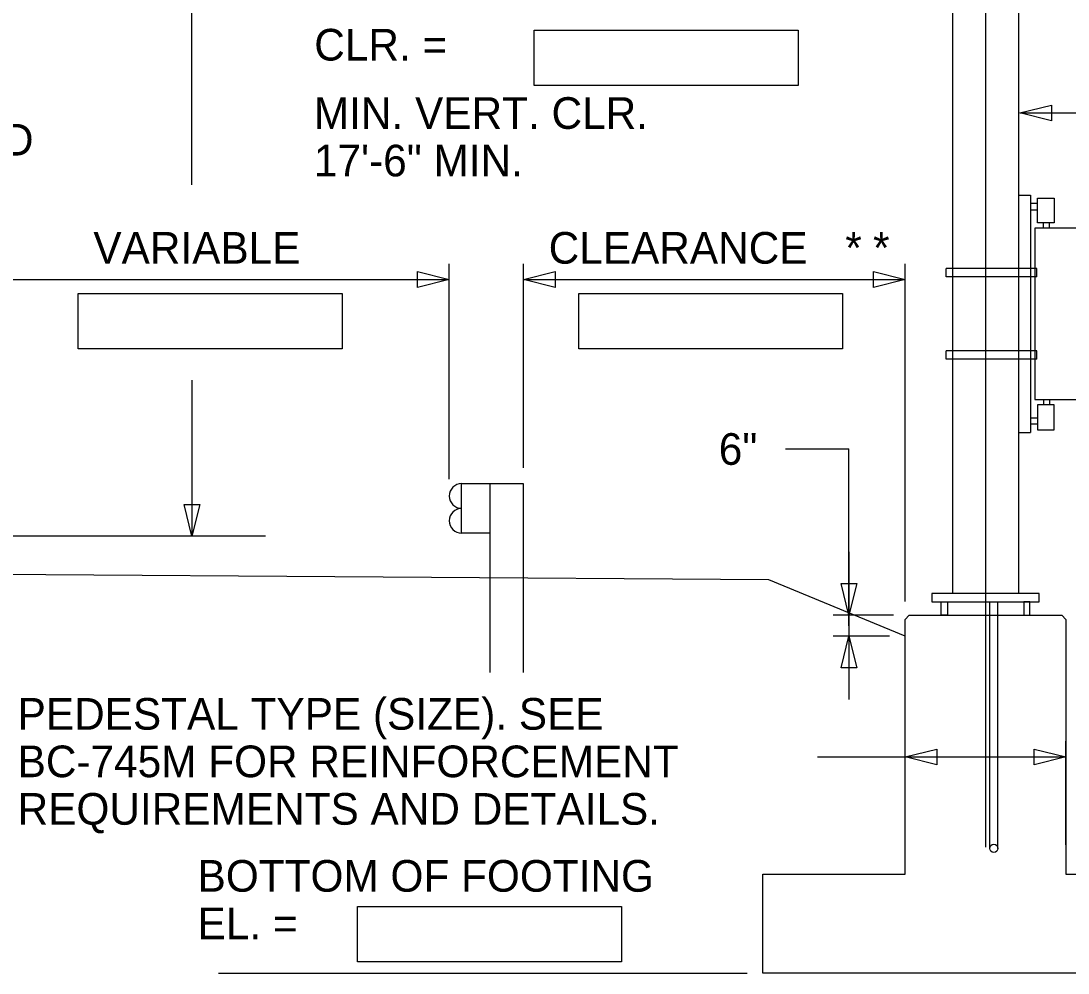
# Model space of a CAD drawing. Extents: x 3831399 to 3833095, y 499014 to 500202.
# Drawn here: x 3832657.9 to 3832754.1, y 499766.9 to 499854.4 of the extents above; entities that cross this region are included whole.
import ezdxf

# ---------------------------------------------------------------- set-up
doc = ezdxf.new("R2010")
doc.units = 0
for name, color, linetype in [('0-ANCHOR', 7, 'Continuous'), ('0-DEVICE ATTACH', 7, 'Continuous'), ('0-foundation', 7, 'Continuous'), ('0-truss', 7, 'Continuous'), ('CenterLine', 7, 'Continuous'), ('Default', 7, 'Continuous'), ('DIM TXT', 7, 'Continuous'), ('grade', 7, 'Continuous'), ('structure', 7, 'Continuous'), ('x-grail', 7, 'Continuous')]:
    doc.layers.add(name, color=color, linetype=linetype)

msp = doc.modelspace()

# ---------------------------------------------------------------- linework, layer by layer
at = {"layer": '0-ANCHOR'}
for p, q in [((3832742.417, 499801.037), (3832742.986, 499801.037)), ((3832742.417, 499799.805), (3832742.417, 499801.037)), ((3832742.986, 499801.037), (3832742.986, 499799.805)), ((3832750.563, 499801.037), (3832749.995, 499801.037)), ((3832749.995, 499801.037), (3832749.995, 499799.805)), ((3832750.563, 499799.805), (3832750.563, 499801.037)), ((3832742.986, 499799.805), (3832742.417, 499799.805)), ((3832749.995, 499799.805), (3832750.563, 499799.805))]:
    msp.add_line(p, q, dxfattribs=at)
at = {"layer": '0-DEVICE ATTACH'}
for p, q in [((3832755.948, 499835.355), (3832751.022, 499835.355)), ((3832751.022, 499835.355), (3832751.022, 499819.631)), ((3832742.853, 499830.903), (3832742.857, 499831.661)), ((3832751.206, 499831.661), (3832742.855, 499831.661)), ((3832751.206, 499830.903), (3832742.855, 499830.903)), ((3832742.853, 499823.325), (3832742.857, 499824.083)), ((3832751.206, 499824.083), (3832742.855, 499824.083)), ((3832751.206, 499823.325), (3832742.855, 499823.325)), ((3832751.022, 499819.631), (3832755.948, 499819.631))]:
    msp.add_line(p, q, dxfattribs=at)
at = {"layer": '0-foundation'}
for p, q in [((3832746.869, 499778.387), (3832746.869, 499801.037)), ((3832747.627, 499778.387), (3832747.627, 499801.037)), ((3832739.102, 499799.426), (3832739.481, 499799.805)), ((3832739.102, 499797.87), (3832739.102, 499799.426)), ((3832739.481, 499799.805), (3832753.5, 499799.805)), ((3832753.5, 499799.805), (3832753.879, 499799.426)), ((3832753.879, 499799.426), (3832753.879, 499797.713)), ((3832739.102, 499776.022), (3832739.102, 499797.87)), ((3832753.879, 499797.713), (3832753.879, 499776.022)), ((3832726.03, 499766.928), (3832726.03, 499776.022)), ((3832726.03, 499776.022), (3832739.102, 499776.022)), ((3832753.879, 499776.022), (3832766.951, 499776.022)), ((3832766.951, 499766.928), (3832726.03, 499766.928))]:
    msp.add_line(p, q, dxfattribs=at)
msp.add_circle((3832747.248, 499778.387), 0.379, dxfattribs=at)
at = {"layer": '0-truss'}
for p, q in [((3832743.459, 499914.154), (3832743.459, 499801.795)), ((3832749.522, 499914.154), (3832749.522, 499801.795)), ((3832751.416, 499801.795), (3832741.565, 499801.795)), ((3832741.565, 499801.795), (3832741.565, 499801.037)), ((3832751.416, 499801.037), (3832751.416, 499801.795)), ((3832741.565, 499801.037), (3832751.416, 499801.037))]:
    msp.add_line(p, q, dxfattribs=at)
at = {"layer": 'CenterLine'}
msp.add_line((3832746.49, 499988.001), (3832746.49, 499778.49), dxfattribs=at)
at = {"layer": 'Default'}
for p, q in [((3832705.024, 499853.562), (3832729.273, 499853.562)), ((3832705.024, 499848.469), (3832705.024, 499853.562)), ((3832729.273, 499853.562), (3832729.273, 499848.469)), ((3832729.273, 499848.469), (3832705.024, 499848.469)), ((3832663.124, 499829.379), (3832687.373, 499829.379)), ((3832663.124, 499824.287), (3832663.124, 499829.379)), ((3832687.373, 499829.379), (3832687.373, 499824.287)), ((3832709.104, 499829.379), (3832733.354, 499829.379)), ((3832709.104, 499824.287), (3832709.104, 499829.379)), ((3832733.354, 499829.379), (3832733.354, 499824.287)), ((3832687.373, 499824.287), (3832663.124, 499824.287)), ((3832733.354, 499824.287), (3832709.104, 499824.287)), ((3832688.784, 499773.056), (3832713.034, 499773.056)), ((3832688.784, 499767.963), (3832688.784, 499773.056)), ((3832713.034, 499773.056), (3832713.034, 499767.963)), ((3832713.034, 499767.963), (3832688.784, 499767.963)), ((3832676.003, 499766.928), (3832724.575, 499766.928))]:
    msp.add_line(p, q, dxfattribs=at)
at = {"layer": 'DIM TXT'}
for p, q in [((3832673.57, 499839.363), (3832673.57, 499873.823)), ((3832749.64, 499845.955), (3832759.482, 499845.949)), ((3832697.193, 499812.312), (3832697.193, 499832.104)), ((3832704.027, 499813.347), (3832704.027, 499832.104)), ((3832739.102, 499801.063), (3832739.102, 499832.104)), ((3832653.975, 499830.649), (3832697.193, 499830.649)), ((3832704.027, 499830.649), (3832739.102, 499830.649)), ((3832673.57, 499821.408), (3832673.57, 499807.083)), ((3832728.103, 499815.078), (3832733.923, 499815.078)), ((3832733.938, 499798.838), (3832733.923, 499815.078)), ((3832572.521, 499807.088), (3832680.32, 499807.088)), ((3832675.947, 499807.083), (3832672.115, 499807.083)), ((3832733.938, 499805.625), (3832733.938, 499799.805)), ((3832738.026, 499799.805), (3832732.483, 499799.805)), ((3832733.938, 499799.805), (3832733.938, 499797.87)), ((3832737.647, 499797.87), (3832732.483, 499797.87)), ((3832733.938, 499797.87), (3832733.938, 499792.05)), ((3832739.102, 499778.708), (3832739.102, 499788.242)), ((3832753.879, 499778.708), (3832753.879, 499788.242)), ((3832731.036, 499786.787), (3832739.102, 499786.787)), ((3832739.102, 499786.787), (3832753.879, 499786.787))]:
    msp.add_line(p, q, dxfattribs=at)
for points in [[(3832752.549, 499845.226), (3832749.64, 499845.955), (3832752.55, 499846.681)], [(3832694.283, 499831.377), (3832697.193, 499830.649), (3832694.283, 499829.922)], [(3832706.937, 499829.922), (3832704.027, 499830.649), (3832706.937, 499831.377)], [(3832736.192, 499831.377), (3832739.102, 499830.649), (3832736.192, 499829.922)], [(3832674.298, 499809.993), (3832673.57, 499807.083), (3832672.843, 499809.993)], [(3832734.666, 499802.715), (3832733.938, 499799.805), (3832733.211, 499802.715)], [(3832733.211, 499794.96), (3832733.938, 499797.87), (3832734.666, 499794.96)], [(3832742.012, 499786.059), (3832739.102, 499786.787), (3832742.012, 499787.514)], [(3832750.969, 499787.514), (3832753.879, 499786.787), (3832750.969, 499786.059)]]:
    msp.add_lwpolyline(points, close=True, dxfattribs=at)
at = {"layer": 'grade'}
for p, q in [((3832726.583, 499803.051), (3832569.141, 499804.175)), ((3832739.102, 499797.87), (3832726.583, 499803.051))]:
    msp.add_line(p, q, dxfattribs=at)
at = {"layer": 'structure'}
for p, q in [((3832749.532, 499838.405), (3832750.628, 499838.405)), ((3832750.628, 499838.395), (3832750.628, 499816.581)), ((3832751.265, 499838.137), (3832752.78, 499838.137)), ((3832751.265, 499835.864), (3832751.265, 499838.137)), ((3832752.78, 499838.137), (3832752.78, 499835.864)), ((3832751.265, 499837.621), (3832750.628, 499837.621)), ((3832750.628, 499837.053), (3832751.265, 499837.053)), ((3832752.78, 499835.864), (3832751.265, 499835.864)), ((3832751.801, 499835.355), (3832751.801, 499835.864)), ((3832752.37, 499835.355), (3832752.37, 499835.864)), ((3832751.206, 499830.903), (3832751.206, 499831.661)), ((3832751.206, 499823.325), (3832751.206, 499824.083)), ((3832751.801, 499819.631), (3832751.801, 499819.122)), ((3832752.37, 499819.631), (3832752.37, 499819.122)), ((3832752.78, 499819.122), (3832751.265, 499819.122)), ((3832751.265, 499819.122), (3832751.265, 499816.848)), ((3832752.78, 499816.848), (3832752.78, 499819.122)), ((3832750.628, 499817.933), (3832751.265, 499817.933)), ((3832751.265, 499817.364), (3832750.628, 499817.364)), ((3832751.265, 499816.848), (3832752.78, 499816.848)), ((3832749.517, 499816.581), (3832750.628, 499816.581))]:
    msp.add_line(p, q, dxfattribs=at)
at = {"layer": 'x-grail'}
for p, q in [((3832698.343, 499807.346), (3832698.343, 499811.892)), ((3832704.027, 499811.892), (3832698.343, 499811.892)), ((3832700.98, 499794.539), (3832700.98, 499811.892)), ((3832704.027, 499794.539), (3832704.027, 499811.892)), ((3832700.98, 499807.346), (3832698.343, 499807.346))]:
    msp.add_line(p, q, dxfattribs=at)
for centre in [(3832698.343, 499810.756), (3832698.343, 499808.482)]:
    msp.add_arc(centre, 1.137, 90, 270, dxfattribs=at)

# ---------------------------------------------------------------- texts
at = {"layer": 'DIM TXT'}
for s, height, p in [('CLR. =', 2.9099, (3832684.806, 499850.768)), ('MIN. VERT. CLR.', 2.90992, (3832684.77, 499844.49)), ('AS REQUIRED', 2.90992, (3832632.199, 499842.039)), ('17\'-6" MIN.', 2.90992, (3832684.77, 499840.125)), ('VARIABLE', 2.9099, (3832664.506, 499832.104)), ('CLEARANCE', 2.9099, (3832706.344, 499832.104)), ('*', 2.91, (3832733.603, 499832.104)), ('*', 2.91, (3832736.152, 499832.104)), ('6"', 2.9099, (3832721.974, 499813.623)), ('PEDESTAL TYPE (SIZE). SEE', 2.90992, (3832657.546, 499789.287)), ('BC-745M FOR REINFORCEMENT', 2.90992, (3832657.546, 499784.922)), ('REQUIREMENTS AND DETAILS.', 2.90992, (3832657.546, 499780.557)), ('BOTTOM OF FOOTING', 2.90992, (3832674.083, 499774.401)), ('EL. =', 2.9099, (3832674.083, 499770.036))]:
    msp.add_text(s, height=height, dxfattribs=at).set_placement(p)

doc.saveas('drawing.dxf')
